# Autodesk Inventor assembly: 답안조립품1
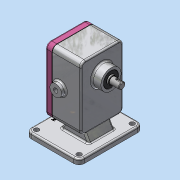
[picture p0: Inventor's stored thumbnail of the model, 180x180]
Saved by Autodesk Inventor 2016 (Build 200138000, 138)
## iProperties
Created: 2020-04
Part Number: 답안조립품1
Material: 일반
Document SubType Name: Assembly
Designer: Administrator
Author: Administrator
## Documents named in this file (11)
- C:\Users\Administrator\Desktop\700407V1029\답안조립품1.iam
- C:\Users\Administrator\Desktop\700407V1029\본체.ipt
- C:\Users\Administrator\Desktop\700407V1029\오일 실 16 28 7.ipt
- C:\Users\Administrator\Desktop\700407V1029\베어링부시.ipt
- C:\Users\Administrator\Desktop\700407V1029\메인축.ipt
- C:\Users\Administrator\Desktop\700407V1029\서브축.ipt
- C:\Users\Administrator\Desktop\700407V1029\키 6 x 6 x 18.ipt
- C:\Users\Administrator\Desktop\700407V1029\스퍼기어.ipt
- C:\Users\Administrator\Desktop\700407V1029\개스킷.ipt
- C:\Users\Administrator\Desktop\700407V1029\커버.ipt
- C:\Users\Administrator\Desktop\700407V1029\볼트 M5.ipt
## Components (1 placed, 1 different names)
1. 개스킷:1
